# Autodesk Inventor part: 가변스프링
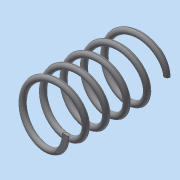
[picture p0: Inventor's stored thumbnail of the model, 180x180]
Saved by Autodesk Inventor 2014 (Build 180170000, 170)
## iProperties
Created: 2024-02
Part Number: 가변스프링
Material: 스테인레스 스틸
Document SubType Name: Modeling
Designer: dg
Density: 8.08 g/cm^3
Appearance: 반연마
Mass: 0.875043 g
Surface Area: 17.7554 cm^2
Volume: 0.875043 cm^3
Author: dg
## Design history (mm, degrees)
sketch "스케치1"
  geometry: L1 (0, 0)-(9, 0); L2 (0, 0)-(0, 28.5); L3 (0, 28.5)-(9, 28.5); C1 r 1 at (9, 0)
  constraints: 6 end point, 2 perpendicular, 1 centre point, 1 coincident, 1 horizontal
  dimensions: "d0" = 9 distance of L1.start L1.end; "d1" = 28.5 distance of L1.start L2.end (derived); "d2" = 1 radius of C1
feature "코일1" pitch "d3" = 10; turns "d5" = 5; dims "d4" = 28.5 (= d1), "d6" = 0, angle "d7" = 90 deg, angle "d8" = 90 deg, "d9" = 0, "d10" = 0
node "작업 평면1"
feature "분할1"
feature "분할2"
node "솔리드1"
other parameters: "d11" = 0
